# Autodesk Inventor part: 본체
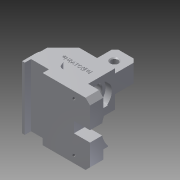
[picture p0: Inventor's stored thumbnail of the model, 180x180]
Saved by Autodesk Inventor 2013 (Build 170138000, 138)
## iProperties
Created: 2016-11
Part Number: 본체
Material: 알루미늄 6061
Document SubType Name: Modeling
Designer: Administrator
Density: 2.71 g/cm^3
Mass: 462.696 g
Surface Area: 317.767 cm^2
Volume: 170.737 cm^3
Author: Administrator
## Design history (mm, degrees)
sketch "스케치1"
  geometry: L1 (0, 0)-(58, 0); L2 (58, 0)-(58, 48); L3 (58, 48)-(0, 48); L4 (0, 48)-(0, 0)
  constraints: 8 end point, 2 parallel, 1 horizontal, 1 perpendicular
  dimensions: "d0" = 48 distance between parallel lines of L1 L3; "d2" = 58 distance of L1.start L1.end
extrude "돌출1" new body sketch "스케치1" stored distance "d3" = 40; taper "d4" = 0 deg
sketch "스케치2"
  geometry: L1 (0, 0)-(0, 48) reference; L2 (0, 48)-(58, 48) reference; L3 (58, 48)-(58, 0) reference; L4 (58, 0)-(0, 0) reference; L5 (14, 3)-(90, 3); L6 (90, 3)-(90, -12); L7 (90, -12)-(14, -12); L8 (14, -12)-(14, 3); C1 r 13 at (27, 3)
  constraints: 8 end point, 2 parallel, 1 centre point, 1 horizontal, 1 perpendicular, 1 point on line, 1 tangent
  dimensions: "d5" = 76 distance of L6.end L7.end; "d7" = 15 distance between parallel lines of L7 L5; "d8" = 90 distance between parallel lines of L6 L1; "d9" = 60 distance between parallel lines of L7 L2; "d10" = 26 diameter of C1
extrude "돌출2" join sketch "스케치2" stored distance "d11" = 70; taper "d12" = 0 deg
sketch "스케치3"
  geometry: L1 (0, 0)-(0, 48) reference; L2 (0, 48)-(58, 48) reference; L3 (58, 48)-(58, 3) reference; L4 (58, 3)-(90, 3) reference; L5 (90, 3)-(90, -12) reference; L6 (90, -12)-(14, -12) reference; L7 (14, -12)-(14, 0) reference; L8 (14, 0)-(0, 0) reference; L9 (58, 48)-(58, 3) reference; L10 (90, -12)-(58, -12); L11 (58, -12)-(58, 8); L12 (58, 8)-(90, 8); L13 (90, 8)-(90, -12)
  constraints: 8 end point, 2 parallel, 1 horizontal, 1 perpendicular, 1 point on line
  dimensions: "d13" = 20 distance between parallel lines of L10 L12
extrude "돌출3" join sketch "스케치3" stored distance "d15" = 40; taper "d16" = 0 deg
sketch "스케치4"
  geometry: L1 (14, 3)-(14, -12) reference; L2 (14, -12)-(90, -12) reference; L3 (90, -12)-(14, -12) reference; L4 (17, -5)-(37, -5); L5 (37, -5)-(37, -12); L6 (37, -12)-(17, -12); L7 (17, -12)-(17, -5); 1 further point
  constraints: 8 end point, 2 parallel, 1 horizontal, 1 perpendicular, 1 point on line
  dimensions: "d17" = 3 distance between parallel lines of L1 L7; "d18" = 7 distance between parallel lines of L2 L4; "d19" = 20 distance between parallel lines of L7 L5
extrude "돌출4" cut sketch "스케치4" stored distance "d20" = 40; taper "d21" = 0 deg
sketch "스케치5"
  geometry: L1 (0, 0)-(0, 48) reference; L2 (0, 48)-(58, 48) reference; L3 (58, 48)-(58, 8) reference; L4 (58, 8)-(90, 8) reference; L5 (90, 8)-(90, -12) reference; L6 (90, -12)-(37, -12) reference; L7 (37, -12)-(37, -5) reference; L8 (37, -5)-(17, -5) reference; L9 (17, -5)-(17, -12) reference; L10 (17, -12)-(14, -12) reference; L11 (14, -12)-(14, 0) reference; L12 (14, 0)-(0, 0) reference; L13 (28, 78)-(53, 78); L14 (53, 78)-(53, 48); L15 (53, 48)-(28, 48); L16 (28, 48)-(28, 78); L17 (40.5, 78)-(40.5, 48); L18 (0, 48)-(58, 48) reference
  constraints: 10 end point, 2 parallel, 2 perpendicular, 2 point on line, 1 horizontal, 1 midpoint
  dimensions: "d22" = 5 distance between parallel lines of L3 L14; "d23" = 25 distance between parallel lines of L14 L16; "d24" = 12.5 distance between parallel lines of L16 L17 (derived); "d25" = 90 distance between parallel lines of L6 L13
extrude "돌출5" join sketch "스케치5" stored distance "d26" = 20; taper "d27" = 0 deg
sketch "스케치6"
  geometry: L1 (0, 0)-(0, 48) reference; L2 (0, 48)-(28, 48) reference; L3 (28, 48)-(28, 78) reference; L4 (28, 78)-(53, 78) reference; L5 (53, 78)-(53, 48) reference; L6 (53, 48)-(58, 48) reference; L7 (58, 48)-(58, 8) reference; L8 (58, 8)-(90, 8) reference; L9 (90, 8)-(90, -12) reference; L10 (90, -12)-(37, -12) reference; L11 (37, -12)-(37, -5) reference; L12 (37, -5)-(17, -5) reference; L13 (17, -5)-(17, -12) reference; L14 (17, -12)-(14, -12) reference; L15 (14, -12)-(14, 0) reference; L16 (14, 0)-(0, 0) reference; L17 (0, 0)-(0, 48) reference; L18 (0, 40)-(51, 40); L19 (58, 44.5)-(58, 30); L20 (0, 30)-(0, 40); L21 (51, 40)-(51, 44.5); L22 (51, 44.5)-(58, 44.5); L23 (0, 30)-(58, 30); L24 (58, 48)-(58, 8) reference
  constraints: 12 end point, 4 point on line, 3 perpendicular, 2 parallel, 1 horizontal
  dimensions: "d31" = 7 distance between parallel lines of L19 L21; "d32" = 30 distance between parallel lines of L16 L23; "d33" = 29 diameter of L22 L23; "d34" = 20 diameter of L18 L23
revolve "회전1" sketch "스케치6" stored, may be unused: angle "d35" = 90 deg
chamfer "모따기1" distance "d36" = 18; stored, may be unused: second distance "d37" = 2, angle "d38" = 45 deg
chamfer "모따기2" distance "d39" = 1; stored, may be unused: second distance "d40" = 2, angle "d41" = 45 deg
chamfer "모따기3" distance "d42" = 4; stored, may be unused: second distance "d43" = 2, angle "d44" = 45 deg
fillet "모깎기1" dims "d45" = 3
sketch "스케치8"
  geometry: L1 (0, 0)-(70, 0) reference; L2 (55, 20)-(15, 20) reference; L3 (29, 13.627)-(29, 0); L4 (0, 0)-(70, 0) reference; L5 (41, 13.627)-(41, 0); L6 (16.106, 20)-(53.894, 20); L7 (15, 20)-(55, 20) reference; L8 (29, 0)-(41, 0); C1 r 14.5 at (35, 42) reference; A1 r 29 centre (35, 42) between (16.106, 20) and (53.894, 20); 1 further point
  constraints: 8 end point, 4 point on circle, 4 point on line, 2 collinear, 2 perpendicular, 1 centre point, 1 coincident
  dimensions: "d56" = 12 distance between parallel lines of L5 L3; "d57" = 6 distance from line of L3 point (35, 12); "d97" = 29 radius of A1
extrude "돌출7" cut sketch "스케치8" distance "d58" = 18; taper "d59" = 0 deg
chamfer "모따기5" distance "d60" = 5; stored, may be unused: second distance "d61" = 2, angle "d62" = 45 deg
fillet "모깎기2" dims "d63" = 5
node "작업 평면1"
sketch "스케치9"
  geometry: L1 (0, 0)-(0, 10) reference; 2 further points
  dimensions: "d64" = 18 distance from line of L1 point (-18, 2.5); "d68" = 27.5 vertical distance of point (-18, 2.5) point (-90, 30)
hole "구멍1" sketch "스케치9" at (-18, 2.5) diameter "d71" = 3.242; stored, may be unused: countersink angle "d75" = 90 deg, drill point angle "d77" = 118 deg; dims "d72" = 6, "d73" = 4, "d74" = 2, "d76" = 8
node "작업 평면2"
sketch "스케치10"
  geometry: L1 (58, 8)-(58, 48) reference; L2 (58, 48)-(18, 48) reference; 2 further points
  constraints: 1 other
  dimensions: "d78" = 25 distance from line of L1 point (33, 30); "d79" = 18 distance from line of point (33, 30) L2
feature "엠보싱1" sketch "스케치10" dims "d0" = 48, "d2" = 58, "d80" = 0.5, "d81" = 0
sketch "스케치11"
  geometry: L1 (28, 74)-(28, 51) reference; L2 (14, -12)-(14, 0) reference; L3 (14, 0)-(0, 0) reference; L4 (0, 0)-(0, 30) reference; L5 (0, 30)-(18, 48) reference; L6 (18, 48)-(25, 48) reference; L7 (28, 51)-(28, 74) reference; L8 (28, 74)-(32, 78) reference; L9 (32, 78)-(49, 78) reference; L10 (49, 78)-(53, 74) reference; L11 (53, 74)-(53, 51) reference; L12 (56, 48)-(58, 48) reference; L13 (58, 48)-(58, 40.5) reference; L14 (58, 40.5)-(51, 40.5) reference; L15 (51, 40.5)-(51, 34.583) reference; L16 (0, 30)-(50, 30) reference; L17 (17, -12)-(14, -12) reference; L18 (17, -5)-(17, -12) reference; L19 (37, -5)-(17, -5) reference; L20 (37, -12)-(37, -5) reference; L21 (90, -12)-(37, -12) reference; L22 (90, 2.779)-(90, -12) reference; L23 (72, 2.779)-(90, 2.779) reference; L24 (72, 8)-(72, 2.779) reference; L25 (58, 8)-(72, 8) reference; L26 (58, 19.5)-(58, 8) reference; L27 (51, 19.5)-(58, 19.5) reference; L28 (51, 25.417)-(51, 19.5) reference; L29 (25, 48)-(56, 48) reference; A1 r 3 centre (25, 51) between (25, 48) and (28, 51) reference; A2 r 3 centre (56, 51) between (53, 51) and (56, 48) reference; 1 further point
  constraints: 2 other
  dimensions: "d82" = 35 distance from line of point (40.5, 65) L16; "d83" = 12.5 distance from line of L1 point (40.5, 65)
hole "구멍2" sketch "스케치11" at (40.5, 65) diameter "d84" = 8; stored, may be unused: countersink angle "d88" = 90 deg, drill point angle "d90" = 118 deg; dims "d85" = 6, "d86" = 4, "d87" = 2, "d89" = 8
chamfer "모따기7" distance "d94" = 1; stored, may be unused: second distance "d95" = 2, angle "d96" = 45 deg
chamfer "모따기8" distance "d98" = 4; stored, may be unused: second distance "d99" = 2, angle "d100" = 45 deg
node "솔리드1"
mirror "대칭1"
node "절단 모서리 투영1"
node "절단 모서리 투영2"
node "절단 모서리 투영3"
node "절단 모서리 투영4"
node "절단 모서리 투영6"
